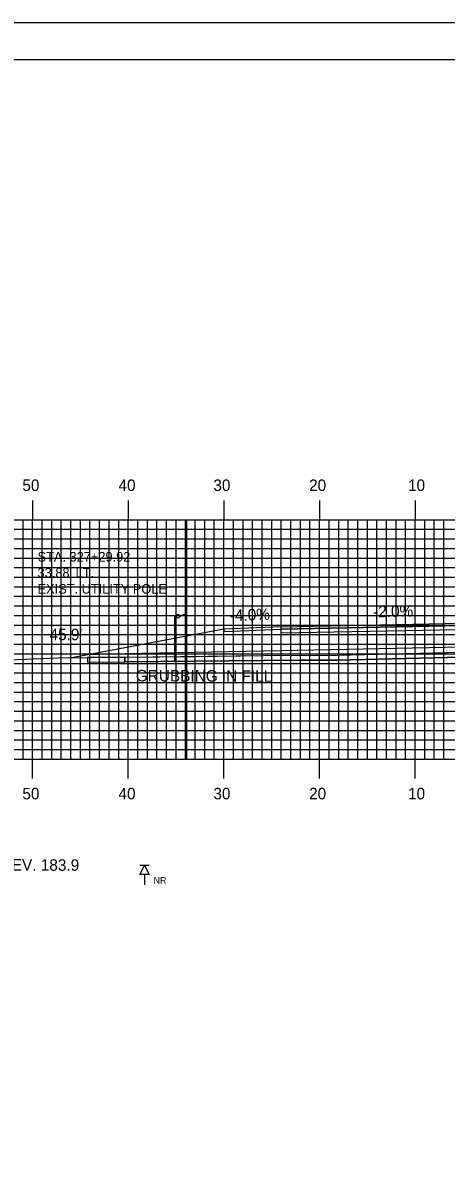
# Model space of a CAD drawing. Extents: x 1821605 to 1821948, y 442591 to 442811.
# Drawn here: x 1821719.7 to 1821764, y 442691.2 to 442810.5 of the extents above; entities that cross this region are included whole.
import ezdxf

# ---------------------------------------------------------------- set-up
doc = ezdxf.new("R2010")
doc.units = 0
for name, color, linetype in [('ANNOTATION', 7, 'Continuous'), ('BORDER', 7, 'Continuous'), ('BORING - NO REFUSAL', 7, 'Continuous'), ('D_Roadway_Edge_Shoulder', 7, 'Continuous'), ('D_Roadway_Edge_TW', 7, 'Continuous'), ('D_Roadway_Pavement', 7, 'Continuous'), ('D_Roadway_SlopeLines', 7, 'Continuous'), ('D_Roadway_SubGrade', 7, 'Continuous'), ('D_Text_Monospaced', 7, 'Continuous'), ('D_Text_Standard', 7, 'Continuous'), ('GRUBBING IN FILL', 7, 'Continuous'), ('H_V ANNOTATION', 7, 'Continuous'), ('M_Utilities_Pole', 7, 'Continuous'), ('MAJOR', 7, 'Continuous'), ('MINOR', 7, 'Continuous'), ('PLOT BOUNDARY', 7, 'Continuous'), ('S_Roadway_Centerline', 7, 'Continuous'), ('S_Utilities_Pole_Power', 7, 'Continuous')]:
    doc.layers.add(name, color=color, linetype=linetype)

msp = doc.modelspace()

# ---------------------------------------------------------------- linework, layer by layer
at = {"layer": 'BORDER'}
msp.add_lwpolyline([(1821621.14, 442596.67), (1821941.14, 442596.67), (1821941.14, 442806.67), (1821621.14, 442806.67)], close=True, dxfattribs=at)
at = {"layer": 'BORING - NO REFUSAL'}
for p, q in [((1821732.92, 442722.57), (1821731.96, 442722.57)), ((1821732.44, 442721.61), (1821732.44, 442720.55))]:
    msp.add_line(p, q, dxfattribs=at)
msp.add_lwpolyline([(1821732.44, 442722.57), (1821732.92, 442721.61), (1821731.96, 442721.61)], close=True, dxfattribs=at)
at = {"layer": 'D_Roadway_Edge_Shoulder'}
msp.add_lwpolyline([(1821746.74, 442747.48), (1821740.74, 442747.24), (1821740.74, 442746.99), (1821746.74, 442747.23)], close=True, dxfattribs=at)
at = {"layer": 'D_Roadway_Edge_TW'}
msp.add_lwpolyline([(1821746.74, 442747.23), (1821746.74, 442747.48), (1821770.74, 442747.96), (1821782.74, 442747.72), (1821782.74, 442747.47), (1821770.74, 442747.71)], close=True, dxfattribs=at)
at = {"layer": 'D_Roadway_Pavement'}
msp.add_lwpolyline([(1821746.74, 442746.81), (1821746.74, 442747.23), (1821770.74, 442747.71), (1821782.74, 442747.47), (1821782.74, 442747.05), (1821770.74, 442747.29)], close=True, dxfattribs=at)
at = {"layer": 'D_Roadway_SlopeLines'}
for p, q in [((1821740.74, 442747.24), (1821724.84, 442744.26)), ((1821730.4, 442744.65), (1821726.49, 442744.57))]:
    msp.add_line(p, q, dxfattribs=at)
msp.add_lwpolyline([(1821726.4, 442743.65), (1821726.36, 442743.66)], dxfattribs=at)
at = {"layer": 'D_Roadway_SubGrade'}
msp.add_lwpolyline([(1821740.74, 442747.24), (1821740.74, 442746.99), (1821746.74, 442747.23), (1821770.74, 442747.71), (1821782.74, 442747.47), (1821792.26, 442747.09), (1821792.26, 442747.34), (1821802.31, 442744.83), (1821782.74, 442745.22), (1821770.74, 442745.46), (1821746.74, 442744.98), (1821730.4, 442744.65)], dxfattribs=at)
at = {"layer": 'GRUBBING IN FILL'}
for p, q in [((1821730.4, 442744.33), (1821726.49, 442744.28)), ((1821730.4, 442744.33), (1821726.49, 442744.28)), ((1821730.4, 442744.33), (1821730.4, 442743.83)), ((1821730.4, 442744.33), (1821730.4, 442743.83)), ((1821730.4, 442743.83), (1821730.4, 442744.33))]:
    msp.add_line(p, q, dxfattribs=at)
for points in [[(1821730.4, 442743.83), (1821744.87, 442743.98), (1821752.59, 442744.01), (1821764.07, 442744.29), (1821775.28, 442744.51), (1821780.99, 442744.77), (1821783.23, 442745.03), (1821783.43, 442745.07), (1821783.66, 442745.11), (1821783.97, 442745.17), (1821784.09, 442745.19)], [(1821730.4, 442743.83), (1821744.87, 442743.98), (1821752.59, 442744.01), (1821764.07, 442744.29), (1821775.28, 442744.51), (1821780.99, 442744.77), (1821783.23, 442745.03), (1821783.43, 442745.07), (1821783.66, 442745.11), (1821783.97, 442745.17), (1821784.09, 442745.19)], [(1821726.49, 442744.28), (1821726.49, 442743.78), (1821730.4, 442743.83)], [(1821726.49, 442744.28), (1821726.49, 442743.78), (1821730.4, 442743.83)]]:
    msp.add_lwpolyline(points, dxfattribs=at)
msp.add_lwpolyline([(1821730.4, 442744.33), (1821737.64, 442744.4), (1821744.87, 442744.48), (1821752.58, 442744.51), (1821758.32, 442744.65), (1821764.06, 442744.79), (1821770.74, 442744.92), (1821770.74, 442744.42), (1821764.07, 442744.29), (1821758.33, 442744.15), (1821752.59, 442744.01), (1821748.73, 442743.99), (1821744.87, 442743.98), (1821737.63, 442743.9), (1821730.4, 442743.83)], close=True, dxfattribs=at)
msp.add_lwpolyline([(1821730.4, 442744.33), (1821737.64, 442744.4), (1821744.87, 442744.48), (1821752.58, 442744.51), (1821758.32, 442744.65), (1821764.06, 442744.79), (1821770.74, 442744.92), (1821770.74, 442744.42), (1821764.07, 442744.29), (1821758.33, 442744.15), (1821752.59, 442744.01), (1821748.73, 442743.99), (1821744.87, 442743.98), (1821737.63, 442743.9), (1821730.4, 442743.83)], close=True, dxfattribs=at)
at = {"layer": 'M_Utilities_Pole'}
msp.add_line((1821736.87, 442745.84), (1821736.87, 442745.83), dxfattribs=at)
msp.add_circle((1821736.87, 442745.83), 0.00417, dxfattribs=at)
at = {"layer": 'MAJOR'}
for p, q in [((1821720.74, 442760.67), (1821720.74, 442758.67)), ((1821730.74, 442760.67), (1821730.74, 442758.67)), ((1821740.74, 442760.67), (1821740.74, 442758.67)), ((1821750.74, 442760.67), (1821750.74, 442758.67)), ((1821760.74, 442760.67), (1821760.74, 442758.67)), ((1821630.74, 442758.67), (1821910.74, 442758.67)), ((1821630.74, 442758.67), (1821910.74, 442758.67)), ((1821720.74, 442733.67), (1821720.74, 442758.67)), ((1821730.74, 442733.67), (1821730.74, 442758.67)), ((1821736.86, 442733.67), (1821736.86, 442758.67)), ((1821740.74, 442733.67), (1821740.74, 442758.67)), ((1821740.74, 442733.67), (1821740.74, 442758.67)), ((1821750.74, 442733.67), (1821750.74, 442758.67)), ((1821760.74, 442733.67), (1821760.74, 442758.67)), ((1821630.74, 442753.67), (1821910.74, 442753.67)), ((1821630.74, 442748.67), (1821910.74, 442748.67)), ((1821630.74, 442743.67), (1821910.74, 442743.67)), ((1821630.74, 442738.67), (1821910.74, 442738.67)), ((1821630.74, 442733.67), (1821910.74, 442733.67)), ((1821630.74, 442733.67), (1821910.74, 442733.67)), ((1821720.74, 442731.66), (1821720.74, 442733.67)), ((1821730.74, 442731.66), (1821730.74, 442733.67)), ((1821740.74, 442731.66), (1821740.74, 442733.67)), ((1821750.74, 442731.66), (1821750.74, 442733.67)), ((1821760.74, 442731.66), (1821760.74, 442733.67))]:
    msp.add_line(p, q, dxfattribs=at)
at = {"layer": 'MINOR'}
for p, q in [((1821719.74, 442733.67), (1821719.74, 442758.67)), ((1821721.74, 442733.67), (1821721.74, 442758.67)), ((1821722.74, 442733.67), (1821722.74, 442758.67)), ((1821723.74, 442733.67), (1821723.74, 442758.67)), ((1821724.74, 442733.67), (1821724.74, 442758.67)), ((1821725.74, 442733.67), (1821725.74, 442758.67)), ((1821726.74, 442733.67), (1821726.74, 442758.67)), ((1821727.74, 442733.67), (1821727.74, 442758.67)), ((1821728.74, 442733.67), (1821728.74, 442758.67)), ((1821729.74, 442733.67), (1821729.74, 442758.67)), ((1821731.74, 442733.67), (1821731.74, 442758.67)), ((1821732.74, 442733.67), (1821732.74, 442758.67)), ((1821733.74, 442733.67), (1821733.74, 442758.67)), ((1821734.74, 442733.67), (1821734.74, 442758.67)), ((1821735.74, 442733.67), (1821735.74, 442758.67)), ((1821736.74, 442733.67), (1821736.74, 442758.67)), ((1821737.74, 442733.67), (1821737.74, 442758.67)), ((1821738.74, 442733.67), (1821738.74, 442758.67)), ((1821739.74, 442733.67), (1821739.74, 442758.67)), ((1821741.74, 442733.67), (1821741.74, 442758.67)), ((1821742.74, 442733.67), (1821742.74, 442758.67)), ((1821743.74, 442733.67), (1821743.74, 442758.67)), ((1821744.74, 442733.67), (1821744.74, 442758.67)), ((1821745.74, 442733.67), (1821745.74, 442758.67)), ((1821746.74, 442733.67), (1821746.74, 442758.67)), ((1821747.74, 442733.67), (1821747.74, 442758.67)), ((1821748.74, 442733.67), (1821748.74, 442758.67)), ((1821749.74, 442733.67), (1821749.74, 442758.67)), ((1821751.74, 442733.67), (1821751.74, 442758.67)), ((1821752.74, 442733.67), (1821752.74, 442758.67)), ((1821753.74, 442733.67), (1821753.74, 442758.67)), ((1821754.74, 442733.67), (1821754.74, 442758.67)), ((1821755.74, 442733.67), (1821755.74, 442758.67)), ((1821756.74, 442733.67), (1821756.74, 442758.67)), ((1821757.74, 442733.67), (1821757.74, 442758.67)), ((1821758.74, 442733.67), (1821758.74, 442758.67)), ((1821759.74, 442733.67), (1821759.74, 442758.67)), ((1821761.74, 442733.67), (1821761.74, 442758.67)), ((1821762.74, 442733.67), (1821762.74, 442758.67)), ((1821763.74, 442733.67), (1821763.74, 442758.67)), ((1821630.74, 442757.67), (1821910.74, 442757.67)), ((1821630.74, 442756.67), (1821910.74, 442756.67)), ((1821630.74, 442755.67), (1821910.74, 442755.67)), ((1821630.74, 442754.67), (1821910.74, 442754.67)), ((1821630.74, 442752.67), (1821910.74, 442752.67)), ((1821630.74, 442751.67), (1821910.74, 442751.67)), ((1821630.74, 442750.67), (1821910.74, 442750.67)), ((1821630.74, 442749.67), (1821910.74, 442749.67)), ((1821630.74, 442747.67), (1821910.74, 442747.67)), ((1821630.74, 442746.67), (1821910.74, 442746.67)), ((1821630.74, 442745.67), (1821910.74, 442745.67)), ((1821630.74, 442744.67), (1821910.74, 442744.67)), ((1821630.74, 442742.67), (1821910.74, 442742.67)), ((1821630.74, 442741.67), (1821910.74, 442741.67)), ((1821630.74, 442740.67), (1821910.74, 442740.67)), ((1821630.74, 442739.67), (1821910.74, 442739.67)), ((1821630.74, 442737.67), (1821910.74, 442737.67)), ((1821630.74, 442736.67), (1821910.74, 442736.67)), ((1821630.74, 442735.67), (1821910.74, 442735.67)), ((1821630.74, 442734.67), (1821910.74, 442734.67))]:
    msp.add_line(p, q, dxfattribs=at)
at = {"layer": 'PLOT BOUNDARY'}
msp.add_lwpolyline([(1821604.96, 442590.55), (1821944.96, 442590.55), (1821944.96, 442810.55), (1821604.96, 442810.55)], close=True, dxfattribs=at)
at = {"layer": 'S_Roadway_Centerline'}
msp.add_lwpolyline([(1821715.67, 442743.93), (1821723.41, 442744.25), (1821730.23, 442744.33), (1821730.42, 442744.33), (1821744.87, 442744.48), (1821752.58, 442744.51), (1821764.06, 442744.79)], dxfattribs=at)
at = {"layer": 'S_Utilities_Pole_Power'}
for p, q in [((1821735.61, 442748.59), (1821735.77, 442748.7)), ((1821735.61, 442743.97), (1821735.62, 442748.59)), ((1821735.77, 442748.48), (1821735.61, 442748.59)), ((1821736.08, 442748.7), (1821736.24, 442748.59)), ((1821736.24, 442748.59), (1821736.08, 442748.48)), ((1821736.39, 442748.7), (1821736.24, 442748.59)), ((1821736.86, 442748.59), (1821736.71, 442748.7)), ((1821736.86, 442743.97), (1821736.87, 442748.59))]:
    msp.add_line(p, q, dxfattribs=at)
for centre, start, end in [((1821735.93, 442748.48), 90, 125.2644), ((1821735.93, 442748.7), 234.7356, 270), ((1821735.93, 442748.48), 54.7356, 90), ((1821735.93, 442748.7), 270, 305.2644), ((1821736.55, 442748.48), 90, 125.2644), ((1821736.55, 442748.48), 54.7356, 90)]:
    msp.add_arc(centre, 0.271, start, end, dxfattribs=at)

# ---------------------------------------------------------------- texts
at = {"layer": 'ANNOTATION'}
for s, rotation, p in [('-4.0%', 2.2906, (1821741.38, 442748.06)), ('-2.0%', 1.1458, (1821756.35, 442748.47))]:
    msp.add_text(s, height=1.2, rotation=rotation, dxfattribs=at).set_placement(p)
at = {"layer": 'BORING - NO REFUSAL'}
msp.add_text('APPROX. ELEV. 183.9', height=1.2, rotation=359.8142, dxfattribs=at).set_placement((1821709.02, 442722.06))
msp.add_text('NR', height=0.7, dxfattribs=at).set_placement((1821733.38, 442720.65))
at = {"layer": 'D_Text_Monospaced'}
for s, p in [('STA. 327+29.92', (1821721.26, 442754.3)), ("33.88' LT.", (1821721.26, 442752.63)), ('EXIST. UTILITY POLE', (1821721.26, 442750.95))]:
    msp.add_text(s, height=1, dxfattribs=at).set_placement(p)
at = {"layer": 'D_Text_Standard'}
msp.add_text("45.9'", height=1.2, dxfattribs=at).set_placement((1821722.51, 442746.09))
at = {"layer": 'GRUBBING IN FILL'}
msp.add_text('GRUBBING IN FILL', height=1.2, rotation=359.8053, dxfattribs=at).set_placement((1821731.53, 442741.79))
at = {"layer": 'H_V ANNOTATION'}
for s, p in [('50', (1821719.67, 442761.67)), ('40', (1821729.72, 442761.67)), ('30', (1821739.64, 442761.67)), ('20', (1821749.65, 442761.67)), ('10', (1821759.99, 442761.67)), ('50', (1821719.67, 442729.47)), ('40', (1821729.72, 442729.47)), ('30', (1821739.64, 442729.47)), ('20', (1821749.65, 442729.47)), ('10', (1821759.99, 442729.47))]:
    msp.add_text(s, height=1.2, dxfattribs=at).set_placement(p)

doc.saveas('drawing.dxf')
